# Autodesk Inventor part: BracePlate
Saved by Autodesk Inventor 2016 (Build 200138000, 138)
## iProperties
Created: 2016-03
Part Number: BracePlate
Material: Generic
Document SubType Name: Modeling
Designer: bongo_000
Density: 1 g/cm^3
Appearance: Default
Author: bongo_000
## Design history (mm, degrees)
feature "Base1"
body "Solid1"
